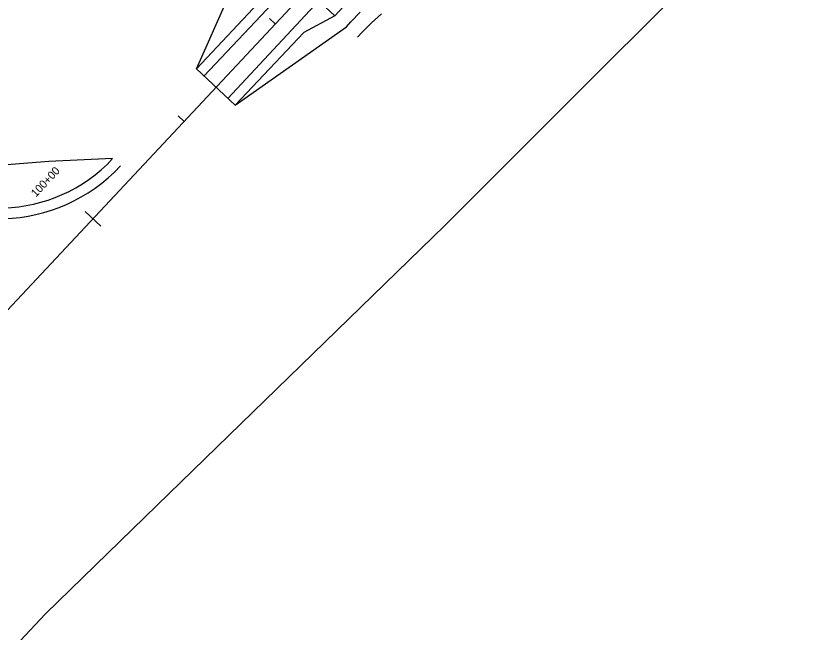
# Model space of a CAD drawing. Extents: x 979959 to 994833, y 1835619 to 1845316.
# Drawn here: x 991864 to 992458, y 1838738 to 1839201 of the extents above; entities that cross this region are included whole.
import ezdxf

# ---------------------------------------------------------------- set-up
doc = ezdxf.new("R2010")
doc.units = 0
for name, color, linetype in [('43', 7, 'Continuous'), ('Future 5 Lane Construction Limits', 7, 'Continuous'), ('R_Horz Alg', 7, 'Continuous'), ('R_Horz Alg Stationing', 7, 'Continuous'), ('R_Proposed Const Limits', 7, 'Continuous'), ('R_Proposed Road', 7, 'Continuous'), ('R_Proposed Road Future', 7, 'Continuous')]:
    doc.layers.add(name, color=color, linetype=linetype)

msp = doc.modelspace()

# ---------------------------------------------------------------- linework, layer by layer
at = {"layer": '43'}
msp.add_lwpolyline([(991703.96, 1838557.9), (991886.39, 1838752.16), (991960.93, 1838824.66), (992185.78, 1839043.33), (992458.22, 1839315.8)], dxfattribs=at)
at = {"layer": 'Future 5 Lane Construction Limits'}
msp.add_lwpolyline([(992120.41, 1839184.65), (992123.82, 1839188.23), (992123.86, 1839188.27), (992130.96, 1839195.33), (992138.39, 1839202.07)], dxfattribs=at)
at = {"layer": 'R_Horz Alg'}
msp.add_line((991717.11, 1838829.33), (992201.25, 1839346.88), dxfattribs=at)
at = {"layer": 'R_Horz Alg Stationing'}
for points in [[(992054.3, 1839198.57), (992058.68, 1839194.47)], [(991985.98, 1839125.54), (991990.36, 1839121.44)], [(991916.21, 1839053.88), (991927.89, 1839042.95)]]:
    msp.add_lwpolyline(points, dxfattribs=at)
at = {"layer": 'R_Proposed Const Limits'}
msp.add_line((991999.62, 1839160.71), (992042.63, 1839257.41), dxfattribs=at)
for points in [[(992028.7, 1839133.51), (992112.1, 1839192.42), (992115.43, 1839196.16), (992122.29, 1839203.44)], [(991936.82, 1839093.48), (991889.08, 1839091.24), (991854.48, 1839088.57), (991820.17, 1839094.54), (991792.22, 1839103.35), (991788.39, 1839106.85), (991780.84, 1839113.41), (991772.74, 1839119.4), (991765.27, 1839126.05), (991758.01, 1839132.93), (991750.48, 1839139.52), (991742.78, 1839145.92), (991735.23, 1839152.49), (991727.8, 1839159.19), (991720.4, 1839165.92)]]:
    msp.add_lwpolyline(points, dxfattribs=at)
at = {"layer": 'R_Proposed Road'}
for p, q in [((992103.4, 1839200.56), (992221.33, 1839328.09)), ((992067.98, 1839233.69), (991999.62, 1839160.71)), ((992073.83, 1839228.23), (992005.28, 1839155.42)), ((992091.35, 1839211.83), (992023.29, 1839138.57)), ((992103.4, 1839200.56), (992096.46, 1839207.05)), ((991999.62, 1839160.71), (992028.7, 1839133.51))]:
    msp.add_line(p, q, dxfattribs=at)
msp.add_lwpolyline([(992103.4, 1839200.56), (992080.27, 1839187.97), (992028.7, 1839133.51)], dxfattribs=at)
at = {"layer": 'R_Proposed Road Future'}
for radius in [117, 125]:
    msp.add_arc((991851.38, 1839173.41), radius, 226.91039, 316.91039, dxfattribs=at)

# ---------------------------------------------------------------- texts
at = {"layer": 'R_Horz Alg Stationing'}
msp.add_text('100+00', height=6, rotation=46.91039, dxfattribs=at).set_placement((991879.32, 1839064.22))

doc.saveas('drawing.dxf')
